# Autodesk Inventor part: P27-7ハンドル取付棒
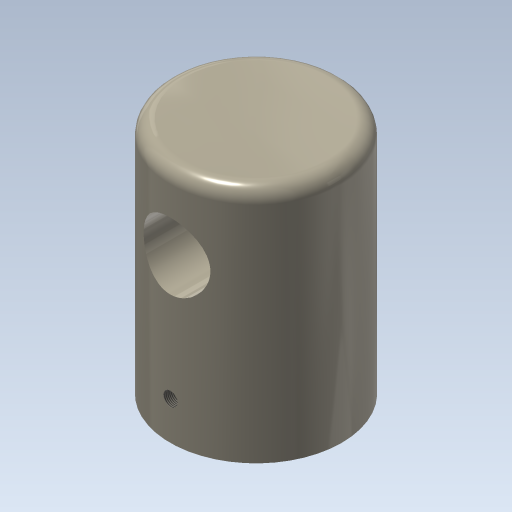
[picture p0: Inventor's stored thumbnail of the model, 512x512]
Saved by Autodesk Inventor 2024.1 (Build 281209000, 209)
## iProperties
Created: 2008-07
Part Number: P27-7ハンドル取付棒
Document SubType Name: Modeling
Designer: y-shimohigashi
Density: 1 g/cm^3
Stock Number: P24-7ハンドル取付棒
Material: 一般
Appearance: 淡いベージュ
Author: y-shimohigashi
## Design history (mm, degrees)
sketch "スケッチ1"
  geometry: C1 r 18 at (0, 0); 1 further point
  constraints: 1 centre point, 1 coincident
  dimensions: "d0" = 36 diameter of C1
extrude "押し出し1" new body sketch "スケッチ1" distance "d1" = 50; taper "d2" = 0 deg
sketch "スケッチ2"
  geometry: L1 (0, 22.4)-(0, 54.6) reference; L2 (-18, 50)-(18, 50) reference; C1 r 7 at (0, 34)
  constraints: 1 centre point, 1 point on line
  dimensions: "d3" = 14 diameter of C1; "d4" = 16 distance from line of L2 C1.centre
extrude "押し出し2" cut sketch "スケッチ2" extent not by distance; stored distance "d5" = 50; taper "d6" = 0 deg
sketch "スケッチ3"
  geometry: L1 (0, -1.9)-(0, 11.4) reference; L2 (-18, 0)-(18, 0) reference; C1 r 1.5 at (0, 8)
  constraints: 1 centre point, 1 point on line
  dimensions: "d7" = 3 diameter of C1; "d8" = 8 distance from line of L2 C1.centre
extrude "押し出し3" cut sketch "スケッチ3" extent not by distance; stored distance "d9" = 50; taper "d10" = 0 deg
feature "ねじ1" dims "d11" = 10, "d12" = 0
fillet "フィレット1" dims "d13" = 3
sketch "スケッチ4"
  geometry: L1 (3.536, -3.536)-(-3.536, -3.536); L2 (-3.536, -3.536)-(-3.536, 3.536); L3 (-3.536, 3.536)-(3.536, 3.536); L4 (3.536, 3.536)-(3.536, -3.536); L5 (3.536, 3.536)-(-3.536, -3.536); 2 further points
  constraints: 10 end point, 2 parallel, 2 perpendicular, 1 coincident, 1 horizontal, 1 midpoint
  dimensions: "d14" = 10 distance of L3.end L1.end
extrude "押し出し4" cut sketch "スケッチ4" stored distance "d15" = 50; taper "d16" = 0 deg
node "ソリッド1"
node "ソリッド ボディ"
node "サーフェス ボディ"
